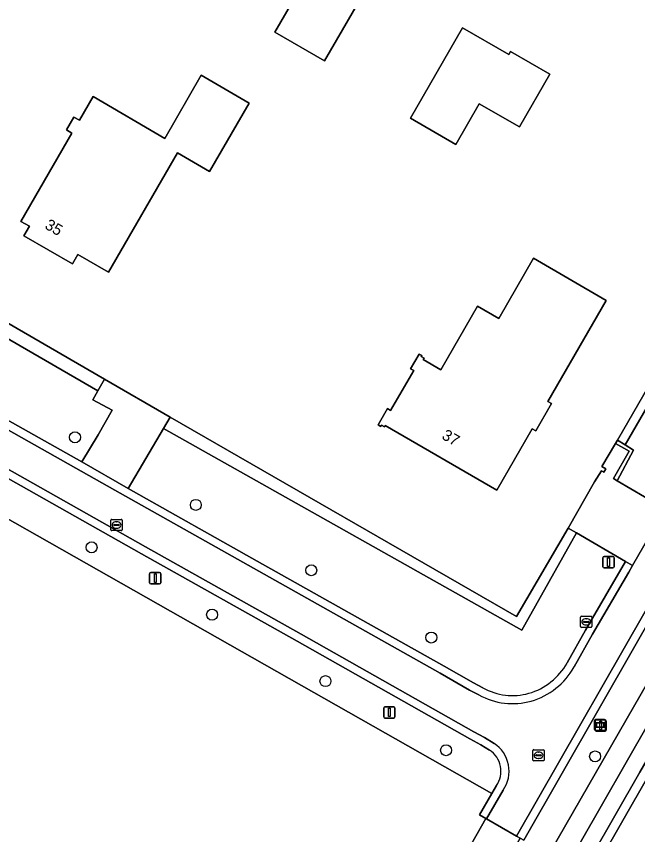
# Model space of a CAD drawing. Extents: x 156502 to 159075, y 384229 to 386100.
# Drawn here: x 157215.2 to 157270.5, y 385635.1 to 385707.8 of the extents above; entities that cross this region are included whole.
import ezdxf

# ---------------------------------------------------------------- set-up
doc = ezdxf.new("R2010")
doc.units = 0
for name, color, linetype in [('IMGEO_Boom', 7, 'Continuous'), ('IMGEO_Brandkraan', 7, 'Continuous'), ('IMGEO_Erf', 7, 'Continuous'), ('IMGEO_Gemengd_bos', 7, 'Continuous'), ('IMGEO_Grasland_agrarisch', 7, 'Continuous'), ('IMGEO_Greppel_droge_sloot', 7, 'Continuous'), ('IMGEO_Groenvoorziening', 7, 'Continuous'), ('IMGEO_Haag', 7, 'Continuous'), ('IMGEO_Hek', 7, 'Continuous'), ('IMGEO_Lichtmast', 7, 'Continuous'), ('IMGEO_Oever', 7, 'Continuous'), ('IMGEO_Pand', 7, 'Continuous'), ('IMGEO_Pand_nummerreeks', 7, 'Continuous'), ('IMGEO_Rijbaan_lokaal_gesloten', 7, 'Continuous'), ('IMGEO_Rijbaan_lokaal_halfverhard', 7, 'Continuous'), ('IMGEO_Rijbaan_lokaal_open', 7, 'Continuous'), ('IMGEO_Rioolput', 7, 'Continuous'), ('IMGEO_Verklikker', 7, 'Continuous')]:
    doc.layers.add(name, color=color, linetype=linetype)

msp = doc.modelspace()

# ---------------------------------------------------------------- linework, layer by layer
at = {"layer": 'IMGEO_Boom'}
for centre in [(157220.385, 385670.394), (157231.144, 385664.386), (157221.866, 385660.603), (157241.417, 385658.57), (157232.595, 385654.618), (157252.104, 385652.586), (157242.683, 385648.703), (157253.419, 385642.561), (157266.683, 385642.007)]:
    msp.add_circle(centre, 0.489, dxfattribs=at)
at = {"layer": 'IMGEO_Brandkraan'}
for p, q in [((157265.394, 385653.553), (157265.394, 385654.405)), ((157265.469, 385654.479), (157266.321, 385654.479)), ((157265.882, 385654.259), (157265.907, 385654.259)), ((157266.395, 385654.405), (157266.395, 385653.553)), ((157266.321, 385653.479), (157265.469, 385653.479)), ((157265.653, 385653.973), (157265.653, 385653.985)), ((157266.091, 385653.936), (157265.693, 385653.936)), ((157265.696, 385654.022), (157266.094, 385654.022)), ((157265.905, 385653.699), (157265.88, 385653.699)), ((157266.137, 385653.985), (157266.137, 385653.973))]:
    msp.add_line(p, q, dxfattribs=at)
for points in [[(157265.394, 385653.553), (157265.394, 385654.405)], [(157265.469, 385654.479), (157266.321, 385654.479)], [(157266.395, 385654.405), (157266.395, 385653.553)], [(157266.321, 385653.479), (157265.469, 385653.479)]]:
    msp.add_lwpolyline(points, dxfattribs=at)
for centre, radius, start, end in [((157265.471, 385654.403), 0.0765, 91.55205, 178.44795), ((157265.471, 385654.403), 0.0765, 91.55205, 178.44795), ((157266.319, 385654.403), 0.0765, 1.55205, 88.44795), ((157266.319, 385654.403), 0.0765, 1.55205, 88.44795), ((157265.471, 385653.555), 0.0765, 181.55205, 268.44795), ((157265.471, 385653.555), 0.0765, 181.55205, 268.44795), ((157265.693, 385653.982), 0.0403, 85.87752, 175.75265), ((157265.69, 385653.972), 0.0366, 178.93798, 274.71019), ((157266.094, 385653.979), 0.043, 264.86636, 352.45326), ((157266.098, 385653.984), 0.0386, 1.73085, 96.63898), ((157266.319, 385653.555), 0.0765, 271.55205, 358.44795), ((157266.319, 385653.555), 0.0765, 271.55205, 358.44795)]:
    msp.add_arc(centre, radius, start, end, dxfattribs=at)
for centre, major_axis, ratio, start_param, end_param in [((157265.881, 385653.979), (-0.387, 0.002), 0.722429, 4.712389, 7.853982), ((157265.906, 385653.979), (-0.39, 0.002), 0.717154, 1.570796, 4.712389)]:
    msp.add_ellipse(centre, major_axis=major_axis, ratio=ratio, start_param=start_param, end_param=end_param, dxfattribs=at)
at = {"layer": 'IMGEO_Erf'}
msp.add_lwpolyline([(157173.064, 385718.503), (157188.558, 385701.554), (157193.621, 385696.088), (157201.359, 385688.107), (157223.003, 385675.555), (157228.873, 385672.175), (157259.687, 385654.464), (157264.272, 385662.327), (157266.64, 385666.428), (157267.252, 385667.419), (157267.448, 385667.3), (157267.622, 385667.589), (157267.294, 385667.793), (157268.496, 385669.844), (157268.668, 385670.142), (157291.965, 385710.53)], dxfattribs=at)
for points in [[(157242.25, 385713.459), (157246.67, 385710.905), (157242.608, 385703.874), (157238.187, 385706.428)], [(157259.94, 385698.001), (157256.358, 385700.067), (157254.274, 385696.456), (157250.249, 385698.779), (157254.891, 385706.823), (157259.002, 385704.451), (157259.152, 385704.71), (157262.648, 385702.694)], [(157235.88, 385700.126), (157232.36, 385694.042), (157229.502, 385695.693), (157223.362, 385685.098), (157220.654, 385686.662), (157220.158, 385685.814), (157215.828, 385688.326), (157216.33, 385689.173), (157215.583, 385689.599), (157220.122, 385697.445), (157219.619, 385697.734), (157220.281, 385698.884), (157220.784, 385698.594), (157222.015, 385700.707), (157228.398, 385696.986), (157231.633, 385702.622)], [(157250.543, 385676.331), (157250.263, 385676.494), (157251.022, 385677.8), (157251.245, 385677.671), (157251.195, 385677.584), (157251.463, 385677.429), (157251.391, 385677.304), (157252.962, 385676.397), (157256.222, 385682.047), (157258.098, 385680.966), (157261.183, 385686.32), (157267.678, 385682.565), (157262.487, 385673.585), (157262.801, 385673.405), (157261.401, 385670.966), (157261.08, 385671.15), (157257.932, 385665.706), (157248.01, 385671.435), (157247.94, 385671.315), (157247.671, 385671.47), (157247.611, 385671.366), (157247.366, 385671.507), (157248.205, 385672.951), (157248.48, 385672.792)]]:
    msp.add_lwpolyline(points, close=True, dxfattribs=at)
at = {"layer": 'IMGEO_Gemengd_bos'}
msp.add_lwpolyline([(157458.702, 385822.569), (157423.669, 385843.007), (157401.006, 385856.043), (157400.448, 385856.357), (157400.325, 385856.13), (157400.025, 385856.299), (157396.132, 385858.496), (157395.472, 385857.325), (157372.587, 385816.736), (157334.959, 385750), (157287.88, 385668.677), (157271.388, 385640.19), (157191.031, 385500)], dxfattribs=at)
at = {"layer": 'IMGEO_Grasland_agrarisch'}
for points in [[(157256.958, 385636.487), (157256.386, 385636.821), (157257.492, 385638.709), (157194.774, 385674.261), (157162.655, 385699.661), (157132.606, 385671.378)], [(157171.409, 385486.07), (157172.284, 385487.327), (157173.759, 385489.447), (157178.241, 385497.482), (157256.958, 385636.487)]]:
    msp.add_lwpolyline(points, dxfattribs=at)
at = {"layer": 'IMGEO_Greppel_droge_sloot'}
for points in [[(157393.364, 385858.054), (157393.108, 385857.612), (157362.753, 385804.111), (157325.818, 385739.168), (157293.922, 385684.217), (157277.506, 385655.557), (157259.264, 385623.708), (157238.621, 385587.751), (157224.85, 385563.789), (157203.074, 385525.899), (157174.272, 385475.365), (157161.248, 385452.051), (157151.078, 385433.934), (157146.7, 385427.265), (157144.863, 385424.97)], [(157146.463, 385424.365), (157148.979, 385428.052), (157150.577, 385430.986), (157151.892, 385433.401), (157190.309, 385500.414), (157270.667, 385640.605), (157287.16, 385669.094), (157334.237, 385750.413), (157371.862, 385817.145), (157394.598, 385857.47)]]:
    msp.add_lwpolyline(points, dxfattribs=at)
at = {"layer": 'IMGEO_Groenvoorziening'}
for points in [[(157293.657, 385701.479), (157297.663, 385708.443), (157292.478, 385711.419), (157291.965, 385710.53), (157292.73, 385710.099), (157269.35, 385669.721), (157270.11, 385669.253), (157268.645, 385666.521), (157272.301, 385664.385), (157273.57, 385666.582), (157284.326, 385685.265)], [(157291.965, 385710.53), (157268.668, 385670.142), (157269.35, 385669.721), (157292.73, 385710.099)], [(157201.359, 385688.107), (157193.621, 385696.088), (157192.885, 385695.422), (157200.392, 385687.281), (157222.414, 385674.517), (157223.003, 385675.555)], [(157265.028, 385661.886), (157264.272, 385662.327), (157259.687, 385654.464), (157228.873, 385672.175), (157228.279, 385671.171), (157260.161, 385653.244)], [(157269.35, 385669.721), (157268.668, 385670.142), (157268.496, 385669.844), (157269.709, 385669.16), (157268.307, 385666.718), (157268.645, 385666.521), (157270.11, 385669.253)]]:
    msp.add_lwpolyline(points, close=True, dxfattribs=at)
for points in [[(157168.762, 385705.12), (157168.384, 385705.534), (157168.522, 385705.66), (157167.865, 385706.331), (157167.579, 385705.215), (157164.874, 385702.768), (157164.798, 385702.861), (157164.374, 385701.279), (157162.655, 385699.661), (157194.774, 385674.261), (157257.492, 385638.709), (157257.907, 385639.417)], [(157199.331, 385680.375), (157221.007, 385668.222), (157222.456, 385670.629), (157223.697, 385672.819), (157221.965, 385673.727), (157222.414, 385674.517), (157200.392, 385687.281), (157192.885, 385695.422)], [(157257.289, 385642.569), (157256.495, 385643.049), (157255.54, 385643.568), (157240.175, 385652.256), (157226.319, 385660.026), (157196.397, 385676.905)], [(157284.199, 385670.89), (157281.966, 385672.234), (157277.603, 385664.635), (157273.616, 385657.789), (157260.323, 385634.562), (157260.023, 385634.734), (157258.636, 385632.327), (157175.427, 385485.533)], [(157228.279, 385671.171), (157225.122, 385665.836), (157236.616, 385659.381), (157253.232, 385650.034), (157255.851, 385648.542), (157256.698, 385648.11)], [(157264.179, 385650.319), (157265.836, 385653.246), (157269.39, 385659.346), (157265.028, 385661.886), (157260.161, 385653.244), (157228.279, 385671.171)], [(157162.512, 385481.093), (157172.104, 385476.13), (157284.199, 385670.89)]]:
    msp.add_lwpolyline(points, dxfattribs=at)
for centre, radius, start, end in [((157259.258, 385653.035), 5.621, 285.73079, 331.10175), ((157259.32, 385652.748), 5.328, 240.52423, 285.93076), ((157256.055, 385640.69), 2.248, 325.48576, 56.70031)]:
    msp.add_arc(centre, radius, start, end, dxfattribs=at)
at = {"layer": 'IMGEO_Haag'}
msp.add_lwpolyline([(157268.668, 385670.142), (157268.496, 385669.844), (157269.709, 385669.16), (157268.307, 385666.718), (157268.645, 385666.521), (157270.11, 385669.253), (157269.35, 385669.721)], close=True, dxfattribs=at)
at = {"layer": 'IMGEO_Hek'}
msp.add_lwpolyline([(157287.88, 385668.677), (157271.388, 385640.19), (157191.031, 385500)], dxfattribs=at)
at = {"layer": 'IMGEO_Lichtmast'}
for p, q in [((157267.378, 385658.885), (157267.378, 385659.685)), ((157267.378, 385659.685), (157267.378, 385658.885)), ((157267.478, 385659.785), (157268.268, 385659.785)), ((157268.268, 385659.785), (157267.478, 385659.785)), ((157268.368, 385659.685), (157268.368, 385658.885)), ((157268.368, 385658.885), (157268.368, 385659.685)), ((157268.268, 385658.785), (157267.478, 385658.785)), ((157267.478, 385658.785), (157268.268, 385658.785)), ((157227.035, 385657.462), (157227.035, 385658.262)), ((157227.035, 385658.262), (157227.035, 385657.462)), ((157227.135, 385658.362), (157227.925, 385658.362)), ((157227.925, 385658.362), (157227.135, 385658.362)), ((157228.025, 385658.262), (157228.025, 385657.462)), ((157228.025, 385657.462), (157228.025, 385658.262)), ((157227.925, 385657.362), (157227.135, 385657.362)), ((157227.135, 385657.362), (157227.925, 385657.362)), ((157247.866, 385645.521), (157247.866, 385646.321)), ((157247.866, 385646.321), (157247.866, 385645.521)), ((157247.966, 385646.421), (157248.756, 385646.421)), ((157248.756, 385646.421), (157247.966, 385646.421)), ((157248.856, 385646.321), (157248.856, 385645.521)), ((157248.856, 385645.521), (157248.856, 385646.321)), ((157248.756, 385645.421), (157247.966, 385645.421)), ((157247.966, 385645.421), (157248.756, 385645.421)), ((157266.688, 385644.355), (157266.688, 385645.155)), ((157266.688, 385645.155), (157266.688, 385644.355)), ((157266.788, 385645.255), (157267.578, 385645.255)), ((157267.578, 385645.255), (157266.788, 385645.255)), ((157267.678, 385645.155), (157267.678, 385644.355)), ((157267.678, 385644.355), (157267.678, 385645.155)), ((157267.578, 385644.255), (157266.788, 385644.255)), ((157266.788, 385644.255), (157267.578, 385644.255))]:
    msp.add_line(p, q, dxfattribs=at)
for points in [[(157267.798, 385659.66), (157267.948, 385659.66), (157267.948, 385658.91), (157267.798, 385658.91), (157267.798, 385659.66)], [(157227.455, 385658.237), (157227.605, 385658.237), (157227.605, 385657.487), (157227.455, 385657.487), (157227.455, 385658.237)], [(157248.286, 385646.296), (157248.436, 385646.296), (157248.436, 385645.546), (157248.286, 385645.546), (157248.286, 385646.296)], [(157267.108, 385645.13), (157267.258, 385645.13), (157267.258, 385644.38), (157267.108, 385644.38), (157267.108, 385645.13)]]:
    msp.add_lwpolyline(points, dxfattribs=at)
for centre, start, end in [((157267.478, 385659.685), 90, 180), ((157267.478, 385659.685), 90, 180), ((157268.268, 385659.685), 0, 90), ((157268.268, 385659.685), 360, 90), ((157267.478, 385658.885), 180, 270), ((157267.478, 385658.885), 180, 270), ((157268.268, 385658.885), 270, 0), ((157268.268, 385658.885), 270, 0), ((157227.135, 385658.262), 90, 180), ((157227.135, 385658.262), 90, 180), ((157227.925, 385658.262), 0, 90), ((157227.925, 385658.262), 360, 90), ((157227.135, 385657.462), 180, 270), ((157227.135, 385657.462), 180, 270), ((157227.925, 385657.462), 270, 0), ((157227.925, 385657.462), 270, 0), ((157247.966, 385646.321), 90, 180), ((157247.966, 385646.321), 90, 180), ((157248.756, 385646.321), 0, 90), ((157248.756, 385646.321), 360, 90), ((157247.966, 385645.521), 180, 270), ((157247.966, 385645.521), 180, 270), ((157248.756, 385645.521), 270, 0), ((157248.756, 385645.521), 270, 0), ((157266.788, 385645.155), 90, 180), ((157266.788, 385645.155), 90, 180), ((157267.578, 385645.155), 0, 90), ((157267.578, 385645.155), 360, 90), ((157266.788, 385644.355), 180, 270), ((157266.788, 385644.355), 180, 270), ((157267.578, 385644.355), 270, 0), ((157267.578, 385644.355), 270, 0)]:
    msp.add_arc(centre, 0.1, start, end, dxfattribs=at)
at = {"layer": 'IMGEO_Oever'}
for points in [[(157392.248, 385858.973), (157329.731, 385750), (157284.199, 385670.89), (157172.104, 385476.13), (157169.187, 385471.062), (157144.406, 385428.006), (157142.387, 385426.069), (157140.629, 385424.939), (157139.199, 385424.57), (157138.03, 385424.765), (157136.95, 385425.168), (157066.806, 385467.263), (157031.924, 385488.196), (156971.45, 385524.488), (156960.957, 385531.062), (156958.283, 385532.648)], [(157144.863, 385424.97), (157146.7, 385427.265), (157151.078, 385433.934), (157161.248, 385452.051), (157174.272, 385475.365), (157203.074, 385525.899), (157224.85, 385563.789), (157238.621, 385587.751), (157259.264, 385623.708), (157277.506, 385655.557), (157293.922, 385684.217), (157325.818, 385739.168), (157362.753, 385804.111), (157393.108, 385857.612), (157393.364, 385858.054)], [(157146.166, 385421.741), (157150.665, 385429.588), (157152.554, 385432.884), (157191.031, 385500), (157271.388, 385640.19), (157287.88, 385668.677), (157334.959, 385750), (157372.587, 385816.736), (157395.472, 385857.325)], [(157394.598, 385857.47), (157371.862, 385817.145), (157334.237, 385750.413), (157287.16, 385669.094), (157270.667, 385640.605), (157190.309, 385500.414), (157151.892, 385433.401), (157150.577, 385430.986), (157148.979, 385428.052), (157146.463, 385424.365)]]:
    msp.add_lwpolyline(points, dxfattribs=at)
at = {"layer": 'IMGEO_Pand'}
for points in [[(157246.67, 385710.905), (157242.25, 385713.459), (157238.187, 385706.428), (157242.608, 385703.874)], [(157259.94, 385698.001), (157262.648, 385702.694), (157259.152, 385704.71), (157259.002, 385704.451), (157254.891, 385706.823), (157250.249, 385698.779), (157254.274, 385696.456), (157256.358, 385700.067)], [(157229.502, 385695.693), (157232.36, 385694.042), (157235.88, 385700.126), (157231.633, 385702.622), (157228.398, 385696.986), (157222.015, 385700.707), (157220.784, 385698.594), (157220.281, 385698.884), (157219.619, 385697.734), (157220.122, 385697.445), (157215.583, 385689.599), (157216.33, 385689.173), (157215.828, 385688.326), (157220.158, 385685.814), (157220.654, 385686.662), (157223.362, 385685.098)], [(157267.678, 385682.565), (157261.183, 385686.32), (157258.098, 385680.966), (157256.222, 385682.047), (157252.962, 385676.397), (157251.391, 385677.304), (157251.463, 385677.429), (157251.195, 385677.584), (157251.245, 385677.671), (157251.022, 385677.8), (157250.263, 385676.494), (157250.543, 385676.331), (157248.48, 385672.792), (157248.205, 385672.951), (157247.366, 385671.507), (157247.611, 385671.366), (157247.671, 385671.47), (157247.94, 385671.315), (157248.01, 385671.435), (157257.932, 385665.706), (157261.08, 385671.15), (157261.401, 385670.966), (157262.801, 385673.405), (157262.487, 385673.585)]]:
    msp.add_lwpolyline(points, close=True, dxfattribs=at)
at = {"layer": 'IMGEO_Rijbaan_lokaal_gesloten'}
msp.add_lwpolyline([(157258.636, 385632.327), (157260.023, 385634.734), (157259.699, 385634.92), (157257.007, 385636.458), (157256.958, 385636.487), (157178.241, 385497.482), (157173.759, 385489.447), (157172.284, 385487.327), (157175.427, 385485.533)], close=True, dxfattribs=at)
at = {"layer": 'IMGEO_Rijbaan_lokaal_halfverhard'}
msp.add_lwpolyline([(157349.521, 385789.087), (157348.91, 385789.439), (157309.98, 385722.29), (157304.982, 385713.626), (157297.187, 385700.104), (157287.277, 385682.931), (157276.979, 385664.993), (157272.994, 385658.151), (157259.699, 385634.92), (157260.023, 385634.734), (157260.323, 385634.562), (157273.616, 385657.789), (157277.603, 385664.635), (157281.966, 385672.234), (157287.901, 385682.571), (157297.811, 385699.744), (157305.606, 385713.266), (157310.603, 385721.93)], close=True, dxfattribs=at)
for points in [[(157198.978, 385679.748), (157223.934, 385665.69), (157236.263, 385658.753), (157252.876, 385649.408), (157255.495, 385647.916), (157256.344, 385647.483)], [(157225.122, 385665.836), (157221.007, 385668.222), (157199.331, 385680.375)], [(157257.684, 385643.171), (157256.839, 385643.682), (157255.884, 385644.201), (157240.529, 385652.883), (157226.671, 385660.654), (157196.751, 385677.532)], [(157196.397, 385676.905), (157226.319, 385660.026), (157240.175, 385652.256), (157255.54, 385643.568), (157256.495, 385643.049), (157257.289, 385642.569)], [(157256.698, 385648.11), (157255.851, 385648.542), (157253.232, 385650.034), (157236.616, 385659.381), (157225.122, 385665.836)], [(157264.806, 385649.964), (157266.458, 385652.883), (157269.674, 385658.399), (157270.012, 385658.984), (157269.39, 385659.346), (157265.836, 385653.246), (157264.179, 385650.319)], [(157257.907, 385639.417), (157257.492, 385638.709), (157256.386, 385636.821), (157256.958, 385636.487), (157257.007, 385636.458), (157258.5, 385639.009)]]:
    msp.add_lwpolyline(points, dxfattribs=at)
for centre, radius, start, end in [((157259.258, 385653.035), 5.621, 285.73079, 331.10175), ((157259.254, 385653.042), 6.348, 285.749, 330.999), ((157259.32, 385652.748), 5.328, 240.52423, 285.93076), ((157259.32, 385652.749), 6.048, 240.5313, 285.90411), ((157256.055, 385640.69), 2.248, 325.48576, 56.70031), ((157256.054, 385640.69), 2.968, 325.49651, 56.68886)]:
    msp.add_arc(centre, radius, start, end, dxfattribs=at)
at = {"layer": 'IMGEO_Rijbaan_lokaal_open'}
for points in [[(157348.91, 385789.439), (157346.335, 385790.923), (157342.981, 385785.158), (157323.12, 385750.946), (157319.615, 385745.165), (157307.225, 385723.612), (157303.781, 385717.632), (157302.348, 385715.145), (157300.611, 385712.126), (157299.169, 385709.618), (157298.287, 385708.085), (157294.281, 385701.12), (157284.95, 385684.906), (157274.194, 385666.223), (157272.923, 385664.022), (157270.012, 385658.984), (157269.674, 385658.399), (157266.458, 385652.883), (157264.806, 385649.964)], [(157258.5, 385639.009), (157257.007, 385636.458), (157259.699, 385634.92), (157272.994, 385658.151), (157276.979, 385664.993), (157287.277, 385682.931), (157297.187, 385700.104), (157304.982, 385713.626), (157309.98, 385722.29), (157348.91, 385789.439)], [(157256.344, 385647.483), (157255.495, 385647.916), (157252.876, 385649.408), (157236.263, 385658.753), (157223.934, 385665.69), (157198.978, 385679.748)], [(157196.751, 385677.532), (157226.671, 385660.654), (157240.529, 385652.883), (157255.884, 385644.201), (157256.839, 385643.682), (157257.684, 385643.171)]]:
    msp.add_lwpolyline(points, dxfattribs=at)
for points in [[(157228.873, 385672.175), (157223.003, 385675.555), (157222.414, 385674.517), (157221.965, 385673.727), (157223.697, 385672.819), (157222.456, 385670.629), (157221.007, 385668.222), (157225.122, 385665.836), (157228.279, 385671.171)], [(157272.301, 385664.385), (157268.645, 385666.521), (157268.307, 385666.718), (157269.709, 385669.16), (157268.496, 385669.844), (157267.294, 385667.793), (157267.622, 385667.589), (157267.448, 385667.3), (157267.252, 385667.419), (157266.64, 385666.428), (157264.272, 385662.327), (157265.028, 385661.886), (157269.39, 385659.346), (157270.012, 385658.984), (157272.923, 385664.022)]]:
    msp.add_lwpolyline(points, close=True, dxfattribs=at)
for centre, radius, start, end in [((157259.254, 385653.042), 6.348, 285.749, 330.999), ((157259.32, 385652.749), 6.048, 240.5313, 285.90411), ((157256.054, 385640.69), 2.968, 325.49651, 56.68886)]:
    msp.add_arc(centre, radius, start, end, dxfattribs=at)
at = {"layer": 'IMGEO_Rioolput'}
for p, q in [((157223.585, 385662.166), (157223.585, 385663.018)), ((157223.66, 385663.092), (157224.512, 385663.092)), ((157224.586, 385663.018), (157224.586, 385662.166)), ((157223.844, 385662.586), (157223.844, 385662.598)), ((157224.282, 385662.549), (157223.884, 385662.549)), ((157223.887, 385662.635), (157224.285, 385662.635)), ((157224.096, 385662.312), (157224.071, 385662.312)), ((157224.073, 385662.872), (157224.098, 385662.872)), ((157224.328, 385662.598), (157224.328, 385662.586)), ((157224.512, 385662.092), (157223.66, 385662.092)), ((157261.224, 385642.609), (157262.076, 385642.609)), ((157261.149, 385641.683), (157261.149, 385642.535)), ((157261.408, 385642.103), (157261.408, 385642.115)), ((157261.846, 385642.066), (157261.448, 385642.066)), ((157261.451, 385642.152), (157261.849, 385642.152)), ((157261.66, 385641.829), (157261.635, 385641.829)), ((157261.637, 385642.389), (157261.662, 385642.389)), ((157261.892, 385642.115), (157261.892, 385642.103)), ((157262.15, 385642.535), (157262.15, 385641.683)), ((157262.076, 385641.609), (157261.224, 385641.609))]:
    msp.add_line(p, q, dxfattribs=at)
for points in [[(157223.585, 385662.166), (157223.585, 385663.018)], [(157223.66, 385663.092), (157224.512, 385663.092)], [(157224.586, 385663.018), (157224.586, 385662.166)], [(157224.512, 385662.092), (157223.66, 385662.092)], [(157261.224, 385642.609), (157262.076, 385642.609)], [(157261.149, 385641.683), (157261.149, 385642.535)], [(157262.15, 385642.535), (157262.15, 385641.683)], [(157262.076, 385641.609), (157261.224, 385641.609)]]:
    msp.add_lwpolyline(points, dxfattribs=at)
for centre, radius, start, end in [((157223.662, 385663.016), 0.0765, 91.55205, 178.44795), ((157223.662, 385663.016), 0.0765, 91.55205, 178.44795), ((157224.51, 385663.016), 0.0765, 1.55205, 88.44795), ((157224.51, 385663.016), 0.0765, 1.55205, 88.44795), ((157223.884, 385662.595), 0.0403, 85.87752, 175.75265), ((157223.881, 385662.585), 0.0366, 178.93798, 274.71019), ((157224.285, 385662.592), 0.043, 264.86636, 352.45326), ((157224.289, 385662.597), 0.0386, 1.73085, 96.63898), ((157223.662, 385662.168), 0.0765, 181.55205, 268.44795), ((157223.662, 385662.168), 0.0765, 181.55205, 268.44795), ((157224.51, 385662.168), 0.0765, 271.55205, 358.44795), ((157224.51, 385662.168), 0.0765, 271.55205, 358.44795), ((157261.226, 385642.533), 0.0765, 91.55205, 178.44795), ((157261.226, 385642.533), 0.0765, 91.55205, 178.44795), ((157262.074, 385642.533), 0.0765, 1.55205, 88.44795), ((157262.074, 385642.533), 0.0765, 1.55205, 88.44795), ((157261.448, 385642.112), 0.0403, 85.87752, 175.75265), ((157261.445, 385642.102), 0.0366, 178.93798, 274.71019), ((157261.849, 385642.109), 0.043, 264.86636, 352.45326), ((157261.853, 385642.114), 0.0386, 1.73085, 96.63898), ((157261.226, 385641.685), 0.0765, 181.55205, 268.44795), ((157261.226, 385641.685), 0.0765, 181.55205, 268.44795), ((157262.074, 385641.685), 0.0765, 271.55205, 358.44795), ((157262.074, 385641.685), 0.0765, 271.55205, 358.44795)]:
    msp.add_arc(centre, radius, start, end, dxfattribs=at)
for centre, major_axis, ratio, start_param, end_param in [((157224.072, 385662.592), (-0.387, 0.002), 0.722429, 4.712389, 7.853982), ((157224.097, 385662.592), (-0.39, 0.002), 0.717154, 1.570796, 4.712389), ((157261.636, 385642.109), (-0.387, 0.002), 0.722429, 4.712389, 7.853982), ((157261.661, 385642.109), (-0.39, 0.002), 0.717154, 1.570796, 4.712389)]:
    msp.add_ellipse(centre, major_axis=major_axis, ratio=ratio, start_param=start_param, end_param=end_param, dxfattribs=at)
at = {"layer": 'IMGEO_Verklikker'}
for p, q in [((157266.627, 385644.406), (157266.627, 385645.206)), ((157266.627, 385645.206), (157266.627, 385644.406)), ((157266.727, 385645.306), (157267.517, 385645.306)), ((157267.517, 385645.306), (157266.727, 385645.306)), ((157267.617, 385645.206), (157267.617, 385644.406)), ((157267.617, 385644.406), (157267.617, 385645.206)), ((157267.517, 385644.306), (157266.727, 385644.306)), ((157266.727, 385644.306), (157267.517, 385644.306))]:
    msp.add_line(p, q, dxfattribs=at)
for points in [[(157266.728, 385645.038), (157267.516, 385645.038), (157267.516, 385644.574), (157266.728, 385644.574), (157266.728, 385645.038)], [(157266.793, 385644.973), (157266.793, 385644.639), (157267.451, 385644.639), (157267.451, 385644.973), (157266.793, 385644.973)]]:
    msp.add_lwpolyline(points, dxfattribs=at)
for centre, start, end in [((157266.727, 385645.206), 90, 180), ((157266.727, 385645.206), 90, 180), ((157267.517, 385645.206), 0, 90), ((157267.517, 385645.206), 360, 90), ((157266.727, 385644.406), 180, 270), ((157266.727, 385644.406), 180, 270), ((157267.517, 385644.406), 270, 0), ((157267.517, 385644.406), 270, 0)]:
    msp.add_arc(centre, 0.1, start, end, dxfattribs=at)

# ---------------------------------------------------------------- texts
at = {"layer": 'IMGEO_Pand_nummerreeks'}
for s, rotation, p in [('35', 329.87961, (157217.626, 385689.017)), ('37', 329.99993, (157252.958, 385670.31))]:
    msp.add_text(s, height=1, rotation=rotation, dxfattribs=at).set_placement(p)

doc.saveas('drawing.dxf')
